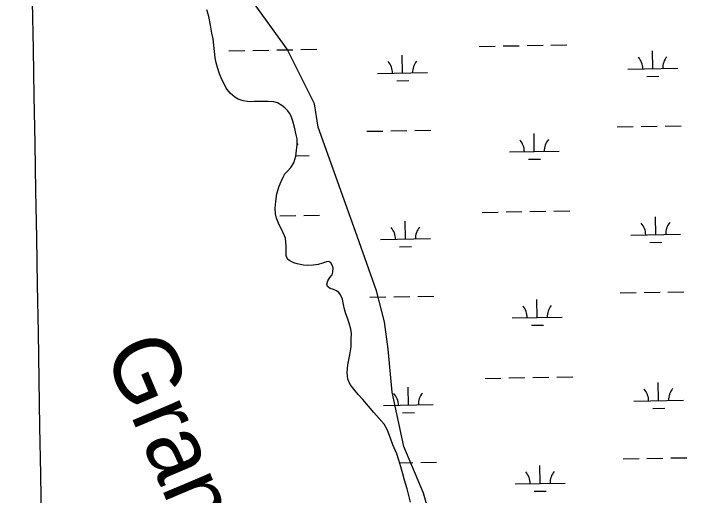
# Model space of a CAD drawing. Extents: x 3903937 to 3942190, y 260677 to 286651.
# Drawn here: x 3913206 to 3914602, y 281121 to 282085 of the extents above; entities that cross this region are included whole.
import ezdxf

# ---------------------------------------------------------------- set-up
doc = ezdxf.new("R2010")
doc.units = 0
for name, color, linetype in [('V-GRID-MAJR', 7, 'Continuous'), ('V-RIVR-IDEN', 7, 'Continuous'), ('V-SITE-VEGE', 7, 'Continuous'), ('V-TOPO-SHOR', 7, 'Continuous'), ('V-UTIL-IDEN', 7, 'Continuous'), ('V-WETL-SWMP', 7, 'Continuous')]:
    doc.layers.add(name, color=color, linetype=linetype)

msp = doc.modelspace()

# ---------------------------------------------------------------- linework, layer by layer
at = {"layer": 'V-GRID-MAJR'}
msp.add_spline([(3913520.414, 266109.772), (3913415.549, 272167.798), (3913310.651, 278227.748), (3913205.754, 284287.69), (3913205.721, 284289.62200000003)], degree=3, dxfattribs=at)
at = {"layer": 'V-SITE-VEGE'}
for p, q in [((3913753.7060000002, 282014.778), (3913652.267, 282155.304)), ((3913808.326, 281905.482), (3913753.7060000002, 282014.778)), ((3913816.129, 281858.643), (3913808.326, 281905.482)), ((3913894.16, 281640.049), (3913816.129, 281858.643)), ((3913933.1720000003, 281530.7539999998), (3913894.16, 281640.049)), ((3913948.7800000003, 281468.298), (3913933.1720000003, 281530.7539999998)), ((3913956.5810000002, 281413.651), (3913948.7800000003, 281468.298)), ((3913964.386, 281327.77400000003), (3913956.5810000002, 281413.651)), ((3913987.795, 281218.479), (3913964.386, 281327.77400000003)), ((3914026.809, 281124.797), (3913987.795, 281218.479)), ((3914058.02, 281023.30599999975), (3914026.809, 281124.797))]:
    msp.add_line(p, q, dxfattribs=at)
at = {"layer": 'V-TOPO-SHOR'}
for points in [[(3913733.273, 281725.222), (3913737.904, 281740.449), (3913741.981, 281749.992), (3913745.965, 281758.541), (3913749.069, 281764.949), (3913754.3140000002, 281770.708), (3913761.278, 281777.974), (3913766.8850000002, 281787.034), (3913770.866, 281800.195), (3913772.37, 281812.165), (3913774.014, 281823.442), (3913773.508, 281834.906), (3913771.798, 281843.24), (3913768.747, 281858.743), (3913764.946, 281870.877), (3913761.5640000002, 281880.468), (3913758.509, 281886.362), (3913755.052, 281891.263), (3913749.307, 281897.276), (3913743.312, 281902.29600000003), (3913734.5470000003, 281907.053), (3913726.967, 281909.021), (3913715.605, 281910.129), (3913705.9960000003, 281910.287), (3913695.228, 281910.078), (3913687.455, 281909.742), (3913681.072, 281909.54), (3913674.463, 281909.802), (3913665.341, 281911.565), (3913655.554, 281914.954), (3913648.539, 281918.606), (3913639.596, 281926.59500000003), (3913631.613, 281936.874), (3913626.693, 281946.414), (3913622.9760000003, 281954.239), (3913617.934, 281965.548), (3913613.903, 281977.84), (3913611.059, 281987.267), (3913609.5330000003, 281997.366), (3913605.156, 282035.5), (3913602.572, 282046.69), (3913600.071, 282063.11100000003), (3913596.889, 282080.154), (3913592.8850000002, 282093.985)], [(3914000.846, 281107.096), (3913994.057, 281133.888), (3913989.183, 281150.962), (3913985.468, 281163.63300000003), (3913981.6240000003, 281177.691), (3913977.919, 281191.13), (3913973.667, 281203.809), (3913965.582, 281221.936), (3913961.1070000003, 281235.234), (3913954.394, 281252.49), (3913948.039, 281263.588), (3913938.2290000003, 281274.97500000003), (3913927.813, 281286.98600000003), (3913917.096, 281299.387), (3913905.315, 281312.574), (3913895.876, 281323.109), (3913887.359, 281333.63), (3913880.287, 281343.126), (3913875.691, 281353.735), (3913873.983, 281366.912), (3913875.548, 281382.57300000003), (3913879.097, 281402.199), (3913881.741, 281418.151), (3913882.378, 281433.59500000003), (3913882.49, 281445.281), (3913881.096, 281453.993), (3913878.364, 281465.648), (3913874.8370000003, 281475.702), (3913871.515, 281484.213), (3913868.6750000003, 281493.871), (3913866.444, 281503.366), (3913864.3880000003, 281513.934), (3913860.989, 281522.369), (3913857.149, 281527.43200000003), (3913852.897, 281530.653), (3913846.708, 281533.06200000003), (3913839.673, 281535.483), (3913834.731, 281539.02400000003), (3913833.269, 281543.585), (3913835.151, 281550.55), (3913839.489, 281557.24700000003), (3913843.648, 281562.408), (3913845.583, 281567.913), (3913846.0300000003, 281576.363), (3913844.125, 281582.238), (3913841.2770000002, 281586.666), (3913837.242, 281589.193), (3913832.47, 281588.886), (3913824.346, 281585.79), (3913815.769, 281583.24), (3913806.061, 281582.091), (3913794.904, 281581.579), (3913786.298, 281581.874), (3913773.576, 281584.465), (3913766.994, 281586.418), (3913759.139, 281590.392), (3913754.667, 281594.309), (3913751.937, 281601.35000000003), (3913751.384, 281619.352), (3913750.116, 281635.904), (3913743.917, 281651.768), (3913740.472, 281657.515), (3913736.1550000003, 281666.19800000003), (3913732.393, 281676.025), (3913730.3880000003, 281685.054), (3913729.798, 281696.058), (3913730.947, 281709.88), (3913733.273, 281725.222)]]:
    msp.add_lwpolyline(points, dxfattribs=at)
at = {"layer": 'V-WETL-SWMP'}
for p, q in [((3913596.889, 282080.155), (3913592.8850000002, 282093.98399999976)), ((3913600.071, 282063.11), (3913596.889, 282080.155)), ((3913602.571, 282046.69099999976), (3913600.071, 282063.11)), ((3913605.157, 282035.4989999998), (3913602.571, 282046.69099999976)), ((3913609.5330000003, 281997.36599999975), (3913605.157, 282035.4989999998)), ((3914138.8105398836, 282020.4330370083), (3914170.8055839, 282020.99620517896)), ((3914186.8031059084, 282021.2777892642), (3914218.7981499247, 282021.8409574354)), ((3914234.7956719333, 282022.1225415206), (3914266.790715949, 282022.68570969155)), ((3914282.7882379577, 282022.967293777), (3914314.783281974, 282023.53046194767)), ((3913636.980272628, 282011.59995543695), (3913668.975316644, 282012.16312360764)), ((3913684.972838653, 282012.4447076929), (3913716.967882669, 282013.00787586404)), ((3913732.9654046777, 282013.28945994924), (3913764.9604486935, 282013.85262812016)), ((3913780.9579707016, 282014.13421220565), (3913812.9530147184, 282014.69738037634)), ((3914486.965758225, 281975.81131178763), (3914486.3321940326, 282011.80573630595)), ((3913611.059, 281987.26799999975), (3913609.5330000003, 281997.36599999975)), ((3913985.1354909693, 281966.97823021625), (3913984.501926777, 282002.9726547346)), ((3913613.904, 281977.84), (3913611.059, 281987.26799999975)), ((3913617.933, 281965.549), (3913613.904, 281977.84)), ((3914436.9735019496, 281974.9313615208), (3914536.958014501, 281976.69126205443)), ((3913622.977, 281954.24), (3913617.933, 281965.549)), ((3913935.1432346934, 281966.09827994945), (3914035.127747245, 281967.8581804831)), ((3913626.694, 281946.413), (3913622.977, 281954.24)), ((3913973.4089197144, 281951.33843202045), (3913997.4052027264, 281951.7608081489)), ((3914475.2391869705, 281960.1715135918), (3914499.235469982, 281960.5938897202)), ((3913631.613, 281936.87499999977), (3913626.694, 281946.413)), ((3913639.596, 281926.59500000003), (3913631.613, 281936.87499999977)), ((3913648.539, 281918.606), (3913639.596, 281926.59500000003)), ((3913655.554, 281914.954), (3913648.539, 281918.60600000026)), ((3913665.341, 281911.56499999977), (3913655.554, 281914.9539999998)), ((3913674.4620000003, 281909.802), (3913665.341, 281911.565)), ((3913681.071, 281909.53999999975), (3913674.4620000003, 281909.8019999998)), ((3913687.4560000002, 281909.743), (3913681.071, 281909.54)), ((3913695.228, 281910.078), (3913687.4560000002, 281909.743)), ((3913705.9960000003, 281910.287), (3913695.228, 281910.078)), ((3913715.606, 281910.13), (3913705.9960000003, 281910.287)), ((3913726.968, 281909.022), (3913715.606, 281910.13)), ((3913734.548, 281907.053), (3913726.968, 281909.022)), ((3913743.313, 281902.29599999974), (3913734.548, 281907.0529999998)), ((3913749.306, 281897.277), (3913743.313, 281902.29600000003)), ((3913755.051, 281891.263), (3913749.306, 281897.277)), ((3913758.508, 281886.3619999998), (3913755.051, 281891.263)), ((3913761.565, 281880.468), (3913758.508, 281886.3619999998)), ((3913764.9450000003, 281870.8779999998), (3913761.565, 281880.468)), ((3913768.7460000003, 281858.744), (3913764.9450000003, 281870.8779999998)), ((3913771.799, 281843.23899999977), (3913768.7460000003, 281858.744)), ((3913913.7703483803, 281850.2721999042), (3913945.7653923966, 281850.8353680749)), ((3913961.7629144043, 281851.1169521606), (3913993.757958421, 281851.6801203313)), ((3914009.7554804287, 281851.961704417), (3914041.7505244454, 281852.52487258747)), ((3914415.600615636, 281859.1052814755), (3914447.5956596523, 281859.66844964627)), ((3914463.5931816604, 281859.95003373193), (3914495.5882256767, 281860.5132019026)), ((3914511.5857476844, 281860.79478598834), (3914543.5807917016, 281861.3579541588)), ((3913773.509, 281834.9069999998), (3913771.799, 281843.23899999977)), ((3914249.379611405, 281809.74231207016), (3914248.7460472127, 281845.7367365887)), ((3913772.369, 281812.165), (3913774.014, 281823.44099999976)), ((3913774.014, 281823.44099999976), (3913773.509, 281834.9069999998)), ((3913770.866, 281800.194), (3913772.369, 281812.165)), ((3914199.3873551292, 281808.86236180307), (3914299.3718676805, 281810.6222623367)), ((3913766.884, 281787.034), (3913770.866, 281800.194)), ((3913771.0076414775, 281801.3221371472), (3913797.541600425, 281801.7891807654)), ((3914237.65304015, 281794.1025138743), (3914261.649323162, 281794.5248900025)), ((3913761.2770000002, 281777.97500000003), (3913766.884, 281787.034)), ((3913749.069, 281764.94799999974), (3913754.315, 281770.707)), ((3913754.315, 281770.707), (3913761.2770000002, 281777.97500000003)), ((3913741.981, 281749.9929999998), (3913745.965, 281758.53999999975)), ((3913745.965, 281758.53999999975), (3913749.069, 281764.94799999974)), ((3913733.273, 281725.222), (3913737.904, 281740.44799999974)), ((3913737.904, 281740.44799999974), (3913741.981, 281749.9929999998)), ((3913730.946, 281709.881), (3913733.273, 281725.222)), ((3913729.798, 281696.059), (3913730.946, 281709.881)), ((3913730.387, 281685.05399999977), (3913729.798, 281696.059)), ((3913732.393, 281676.025), (3913730.387, 281685.05399999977)), ((3914144.6652889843, 281687.80955987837), (3914176.660333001, 281688.37272804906)), ((3914192.657855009, 281688.65431213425), (3914224.652899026, 281689.21748030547)), ((3914240.650421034, 281689.49906439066), (3914272.6454650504, 281690.0622325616)), ((3914288.6429870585, 281690.3438166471), (3914320.638031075, 281690.90698481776)), ((3913736.154, 281666.19799999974), (3913732.393, 281676.025)), ((3913738.820153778, 281680.66598281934), (3913770.8151977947, 281681.22915099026)), ((3913786.812719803, 281681.51073507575), (3913818.8077638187, 281682.07390324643)), ((3913990.9902400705, 281634.35475308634), (3913990.356675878, 281670.34917760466)), ((3914492.820507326, 281643.18783465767), (3914492.186943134, 281679.18225917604)), ((3913740.472, 281657.515), (3913736.154, 281666.19799999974)), ((3913743.916, 281651.76900000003), (3913740.472, 281657.515)), ((3913750.116, 281635.9049999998), (3913743.916, 281651.76900000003)), ((3914442.828251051, 281642.3078843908), (3914542.812763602, 281644.0677849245)), ((3913751.384, 281619.352), (3913750.116, 281635.9049999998)), ((3913940.9979837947, 281633.4748028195), (3914040.982496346, 281635.2347033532)), ((3914481.0939360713, 281627.5480364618), (3914505.0902190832, 281627.97041259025)), ((3913751.936, 281601.34999999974), (3913751.384, 281619.352)), ((3913979.2636688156, 281618.7149548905), (3914003.2599518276, 281619.1373310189)), ((3913754.666, 281594.309), (3913751.936, 281601.34999999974)), ((3913759.139, 281590.391), (3913754.666, 281594.309)), ((3913766.994, 281586.4179999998), (3913759.139, 281590.391)), ((3913773.575, 281584.4649999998), (3913766.994, 281586.4179999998)), ((3913786.2970000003, 281581.874), (3913773.575, 281584.4649999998)), ((3913824.346, 281585.79), (3913815.769, 281583.23899999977)), ((3913832.47, 281588.887), (3913824.346, 281585.79)), ((3913837.242, 281589.193), (3913832.47, 281588.887)), ((3913841.276, 281586.6669999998), (3913837.242, 281589.193)), ((3913844.126, 281582.2379999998), (3913841.276, 281586.6669999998)), ((3913794.904, 281581.58), (3913786.2970000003, 281581.874)), ((3913806.062, 281582.09), (3913794.904, 281581.58)), ((3913815.769, 281583.23899999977), (3913806.062, 281582.09)), ((3913846.029, 281576.363), (3913844.126, 281582.2379999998)), ((3913845.5840000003, 281567.912), (3913846.029, 281576.363)), ((3913835.151, 281550.55), (3913839.489, 281557.24599999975)), ((3913839.489, 281557.24599999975), (3913843.649, 281562.4069999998)), ((3913843.649, 281562.4069999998), (3913845.5840000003, 281567.912)), ((3913833.269, 281543.58399999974), (3913835.151, 281550.55)), ((3913834.7320000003, 281539.023), (3913833.269, 281543.58399999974)), ((3913839.6720000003, 281535.482), (3913834.7320000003, 281539.023)), ((3913846.707, 281533.06099999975), (3913839.6720000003, 281535.4819999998)), ((3913852.896, 281530.653), (3913846.707, 281533.06099999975)), ((3913857.149, 281527.431), (3913852.896, 281530.653)), ((3914517.440496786, 281528.1713088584), (3914549.4355408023, 281528.73447702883)), ((3913860.988, 281522.36999999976), (3913857.149, 281527.431)), ((3913864.3880000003, 281513.934), (3913860.988, 281522.36999999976)), ((3913919.625097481, 281517.6487227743), (3913951.620141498, 281518.211890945)), ((3913967.6176635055, 281518.49347503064), (3913999.6127075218, 281519.05664320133)), ((3914015.6102295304, 281519.33822728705), (3914047.605273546, 281519.9013954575)), ((3914421.4553647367, 281526.4818043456), (3914453.4504087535, 281527.0449725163)), ((3914469.4479307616, 281527.326556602), (3914501.442974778, 281527.8897247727)), ((3913866.4450000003, 281503.366), (3913864.3880000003, 281513.934)), ((3913868.674, 281493.87200000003), (3913866.4450000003, 281503.366)), ((3914255.2343605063, 281477.1188349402), (3914254.600796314, 281513.1132594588)), ((3913871.515, 281484.214), (3913868.674, 281493.87200000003)), ((3913874.8370000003, 281475.701), (3913871.515, 281484.214)), ((3913878.363, 281465.648), (3913874.8370000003, 281475.701)), ((3914205.242104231, 281476.2388846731), (3914305.2266167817, 281477.9987852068)), ((3913881.095, 281453.992), (3913878.363, 281465.648)), ((3914243.5077892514, 281461.47903674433), (3914267.5040722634, 281461.90141287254)), ((3913882.491, 281445.28), (3913881.095, 281453.992)), ((3913882.377, 281433.59499999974), (3913882.491, 281445.28)), ((3913881.741, 281418.15), (3913882.377, 281433.59499999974)), ((3913879.097, 281402.199), (3913881.741, 281418.15)), ((3913875.5470000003, 281382.572), (3913879.097, 281402.199)), ((3913873.984, 281366.912), (3913875.5470000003, 281382.572)), ((3913875.6920000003, 281353.73499999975), (3913873.984, 281366.912)), ((3913880.2860000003, 281343.12599999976), (3913875.6920000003, 281353.73499999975)), ((3914150.520038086, 281355.1860827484), (3914182.515082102, 281355.7492509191)), ((3914198.512604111, 281356.03083500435), (3914230.5076481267, 281356.5940031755)), ((3914246.5051701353, 281356.87558726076), (3914278.5002141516, 281357.4387554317)), ((3914294.4977361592, 281357.7203395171), (3914326.4927801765, 281358.2835076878)), ((3913887.359, 281333.6289999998), (3913880.2860000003, 281343.12599999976)), ((3913895.876, 281323.10999999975), (3913887.359, 281333.6289999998)), ((3913996.8449891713, 281301.7312759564), (3913996.2114249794, 281337.72570047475)), ((3914498.675256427, 281310.56435752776), (3914498.041692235, 281346.5587820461)), ((3913905.316, 281312.575), (3913895.876, 281323.10999999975)), ((3913917.096, 281299.38799999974), (3913905.316, 281312.575)), ((3914448.6830001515, 281309.6844072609), (3914548.667512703, 281311.44430779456)), ((3913927.812, 281286.987), (3913917.096, 281299.38799999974)), ((3913946.852732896, 281300.8513256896), (3914046.837245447, 281302.61122622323)), ((3914486.948685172, 281294.9245593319), (3914510.9449681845, 281295.34693546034)), ((3913938.228, 281274.9759999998), (3913927.812, 281286.987)), ((3913985.1184179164, 281286.0914777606), (3914009.114700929, 281286.513853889)), ((3913948.038, 281263.58899999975), (3913938.228, 281274.9759999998)), ((3913954.393, 281252.49), (3913948.038, 281263.589)), ((3913961.108, 281235.2329999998), (3913954.393, 281252.49)), ((3913965.582, 281221.935), (3913961.108, 281235.2329999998)), ((3913973.668, 281203.80999999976), (3913965.582, 281221.935)), ((3913977.92, 281191.1299999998), (3913973.668, 281203.80999999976)), ((3914427.310113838, 281193.85832721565), (3914459.305157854, 281194.42149538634)), ((3914475.302679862, 281194.70307947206), (3914507.297723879, 281195.26624764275)), ((3914523.295245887, 281195.5478317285), (3914555.290289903, 281196.1109998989)), ((3913981.623, 281177.68999999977), (3913977.92, 281191.1299999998)), ((3913979.3407806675, 281185.9732913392), (3914005.467456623, 281186.4331660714)), ((3914021.464978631, 281186.71475015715), (3914053.4600226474, 281187.2779183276)), ((3914261.089109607, 281144.4953578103), (3914260.455545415, 281180.48978232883)), ((3913985.469, 281163.63300000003), (3913981.623, 281177.68999999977)), ((3913989.183, 281150.962), (3913985.469, 281163.63300000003)), ((3913994.057, 281133.889), (3913989.183, 281150.962)), ((3914211.0968533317, 281143.6154075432), (3914311.081365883, 281145.37530807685)), ((3914000.847, 281107.097), (3913994.057, 281133.889)), ((3914249.362538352, 281128.8555596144), (3914273.3588213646, 281129.27793574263))]:
    msp.add_line(p, q, dxfattribs=at)
for centre, radius, start, end in [((3913929.8927545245, 281966.48073913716), 35.24628790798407, 0.23658072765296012, 41.78023906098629), ((3914040.3615152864, 281968.4251805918), 35.24628790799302, 140.23657772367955, 181.78023605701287), ((3914431.72302178, 281975.31382070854), 35.24628790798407, 0.23658072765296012, 41.78023906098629), ((3914542.1917825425, 281977.25826216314), 35.24628790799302, 140.23657772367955, 181.78023605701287), ((3913802.7753684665, 281802.35618087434), 35.24628790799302, 140.23657772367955, 145.05727664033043), ((3914194.13687496, 281809.24482099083), 35.24628790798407, 0.23658072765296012, 41.78023906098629), ((3914304.605635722, 281811.18926244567), 35.24628790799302, 140.23657772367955, 181.78023605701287), ((3913935.7475036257, 281633.85726200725), 35.24628790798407, 0.23658072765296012, 41.78023906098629), ((3914046.216264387, 281635.8017034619), 35.24628790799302, 140.23657772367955, 181.78023605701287), ((3914437.5777708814, 281642.6903435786), 35.24628790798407, 0.23658072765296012, 41.78023906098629), ((3914548.046531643, 281644.63478503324), 35.24628790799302, 140.23657772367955, 181.78023605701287), ((3914310.460384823, 281478.56578531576), 35.24628790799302, 140.23657772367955, 181.78023605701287), ((3914199.9916240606, 281476.62134386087), 35.24628790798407, 0.23658072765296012, 41.78023906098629), ((3914443.4325199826, 281310.0668664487), 35.24628790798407, 0.23658072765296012, 41.78023906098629), ((3914553.9012807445, 281312.0113079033), 35.24628790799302, 140.23657772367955, 181.78023605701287), ((3913941.6022527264, 281301.2337848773), 35.24628790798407, 0.23658072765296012, 41.78023906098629), ((3914052.071013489, 281303.17822633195), 35.24628790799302, 140.23657772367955, 181.78023605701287), ((3914205.8463731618, 281143.99786673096), 35.24628790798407, 0.23658072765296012, 41.78023906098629), ((3914316.315133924, 281145.9423081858), 35.24628790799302, 140.23657772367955, 181.78023605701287)]:
    msp.add_arc(centre, radius, start, end, dxfattribs=at)

# ---------------------------------------------------------------- texts
at = {"layer": 'V-RIVR-IDEN'}
msp.add_text('Grand', height=132.99973599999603, rotation=292.85806116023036, dxfattribs=at).set_placement((3913385.186861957, 281410.11632204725))
at = {"layer": 'V-UTIL-IDEN'}
msp.add_text('GULF REFINING  CO. 1-10" OIL PIPELINE', height=82.999832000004, rotation=76.30985162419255, dxfattribs=at).set_placement((3914548.6306435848, 280279.77531072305))

doc.saveas('drawing.dxf')
